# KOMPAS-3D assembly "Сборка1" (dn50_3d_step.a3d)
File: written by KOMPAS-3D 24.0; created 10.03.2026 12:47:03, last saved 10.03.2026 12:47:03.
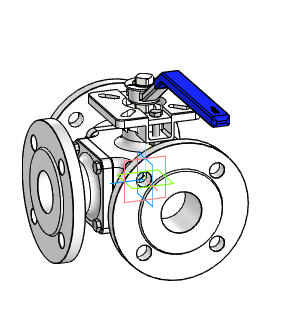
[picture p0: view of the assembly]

Document properties: Автор: R2D2; Полное имя файла: E:\Работа\Зайцев\BV3232P(4pc)-FP-3WL-F-ISO-H Кран шаровой DN.ru Ду15-100 Ру16\DN50\исходные материалы\dn50_3d_step.a3d

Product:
- Component [detail]: Деталь  | qty 1  | Автор: R2D2; source file: Деталь Деталь.m3d
- Component [detail]: Деталь1  | qty 1  | Автор: R2D2; source file: Деталь1 Деталь1.m3d
- Component [detail]: AS 1110 - M8 x 40  | qty 1  | Автор: R2D2; source file: AS 1110 - M8 x 40 AS 1110 - M8 x 40.m3d
- Component [detail]: AS 1110 - M8 x 40  | qty 1  | Комментарий: Болты и винты   шестигранные точные   метрические ISO; Автор: R2D2; additional columns: Сталь, мягкая; source file: AS 1110 - M8 x 40 AS 1110 - M8 x 40.m3d
- Component [detail]: ANSI B18.2.4.2M - M8x1,25 - 13  | designation ANSI B18.2.4.2M - M8x1,25  | qty 1  | Автор: R2D2; source file: ANSI B18.2.4.2M - M8x1,25 ANSI B18.2.4.2M - M8x1,25 - 13.m3d
- Component [detail]: ANSI B18.2.4.2M - M8x1,25 - 13  | designation ANSI B18.2.4.2M - M8x1,25  | qty 1  | Комментарий: Типы метрических   шестигранных гаек   2; Автор: R2D2; additional columns: Сталь, мягкая; source file: ANSI B18.2.4.2M - M8x1,25 ANSI B18.2.4.2M - M8x1,25 - 13.m3d
- Component [detail]: AS 1110 - M8 x 12  | qty 1  | Автор: R2D2; source file: AS 1110 - M8 x 12 AS 1110 - M8 x 12.m3d
- Component [detail]: AS 1110 - M8 x 12  | qty 11  | Комментарий: Болты и винты   шестигранные точные   метрические ISO; Автор: R2D2; additional columns: Сталь, мягкая; source file: AS 1110 - M8 x 12 AS 1110 - M8 x 12.m3d
- Part/product: Сборка1

Referenced files in E:\Работа\Зайцев\BV3232P(4pc)-FP-3WL-F-ISO-H Кран шаровой DN.ru Ду15-100 Ру16\DN50\исходные материалы\: Деталь Деталь.m3d, Деталь1 Деталь1.m3d, AS 1110 - M8 x 40 AS 1110 - M8 x 40.m3d, ANSI B18.2.4.2M - M8x1,25 ANSI B18.2.4.2M - M8x1,25 - 13.m3d, AS 1110 - M8 x 12 AS 1110 - M8 x 12.m3d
